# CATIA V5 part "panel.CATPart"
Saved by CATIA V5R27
Part number: panel
Source: Unknown
Bounding box of the stored display mesh (mm): x -99.978 to 482.113, y -128.148 to 129.908, z -97.11 to 97.137
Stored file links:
  H:\STEP-Test-cases\public\installation-with-fasteners\tc4-assembly-PAG\STEP\panel.CATPart
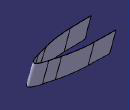
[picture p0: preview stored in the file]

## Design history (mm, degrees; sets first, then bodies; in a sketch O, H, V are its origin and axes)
AxisSystem1: origin (0, 0, 0), X (1, 0, 0), Y (0, 1, 0), Z (0, 0, 1)
Body1 (main body)
  Solid1 "PartBody": solid without history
